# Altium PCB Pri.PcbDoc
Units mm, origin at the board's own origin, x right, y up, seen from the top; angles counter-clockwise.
Board outline 42.69 x 35.5 mm, 4 copper layers (Top Layer, Layer 1, Layer 2, Bottom Layer), stack 1.047 mm thick; 31 components, 16 nets, 112 pads, 246 vias.
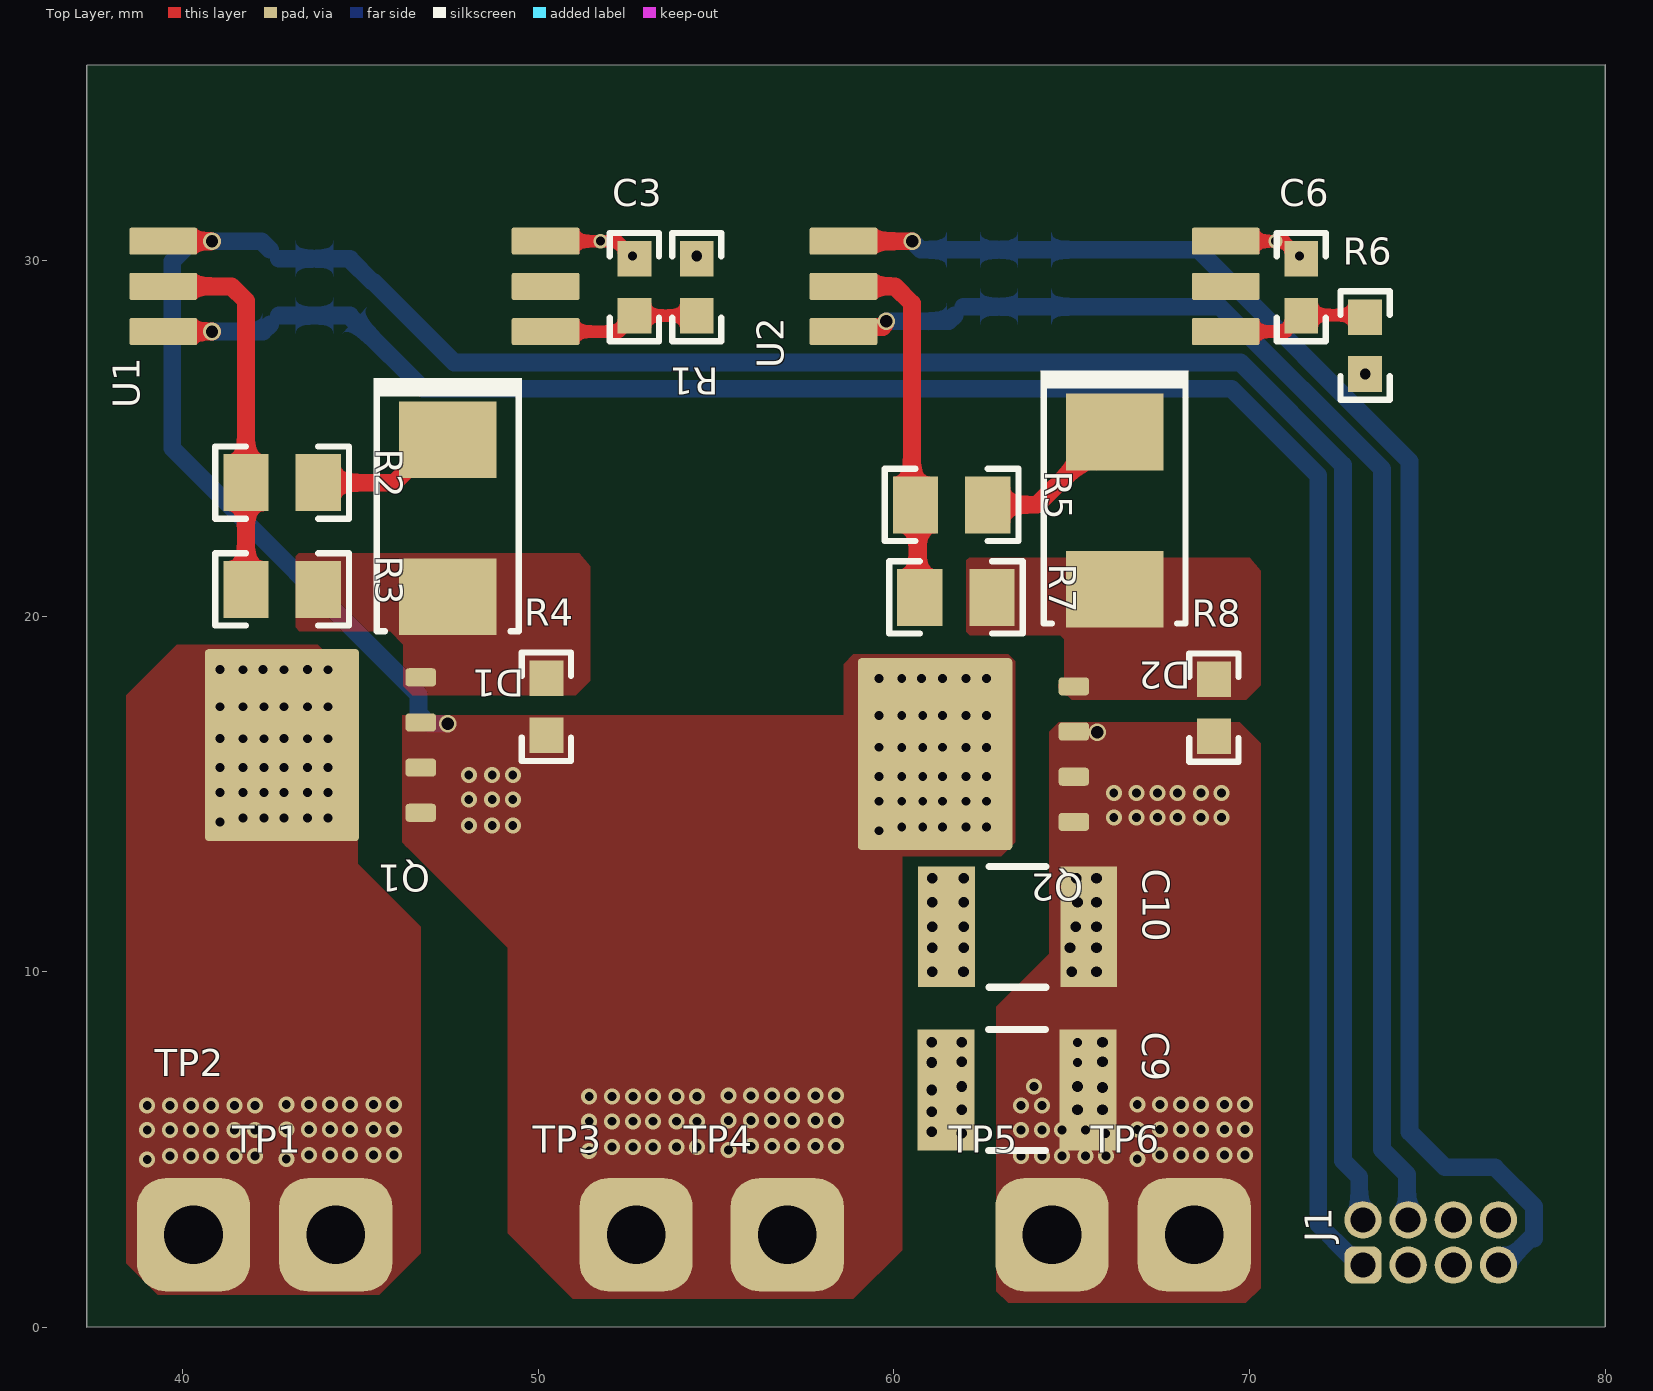
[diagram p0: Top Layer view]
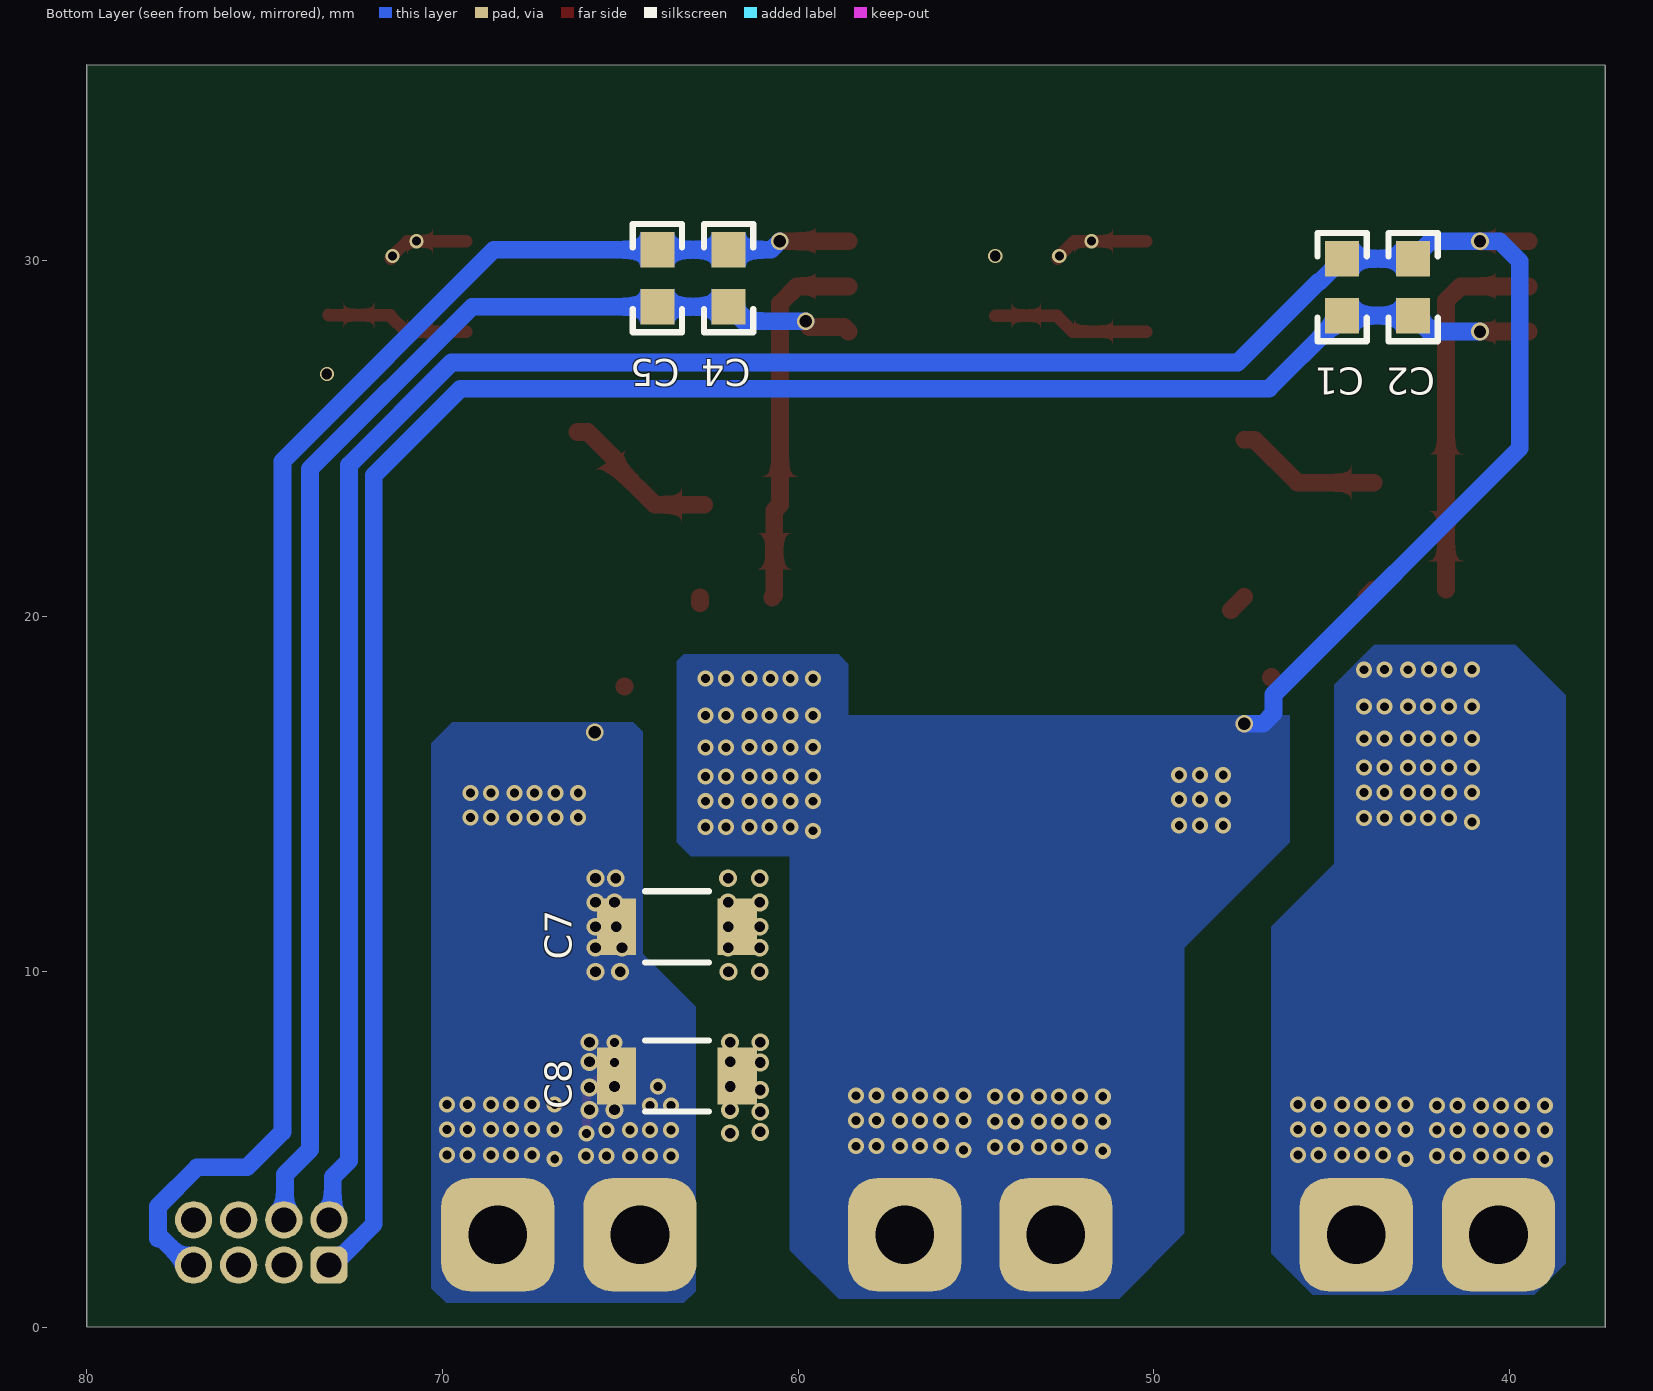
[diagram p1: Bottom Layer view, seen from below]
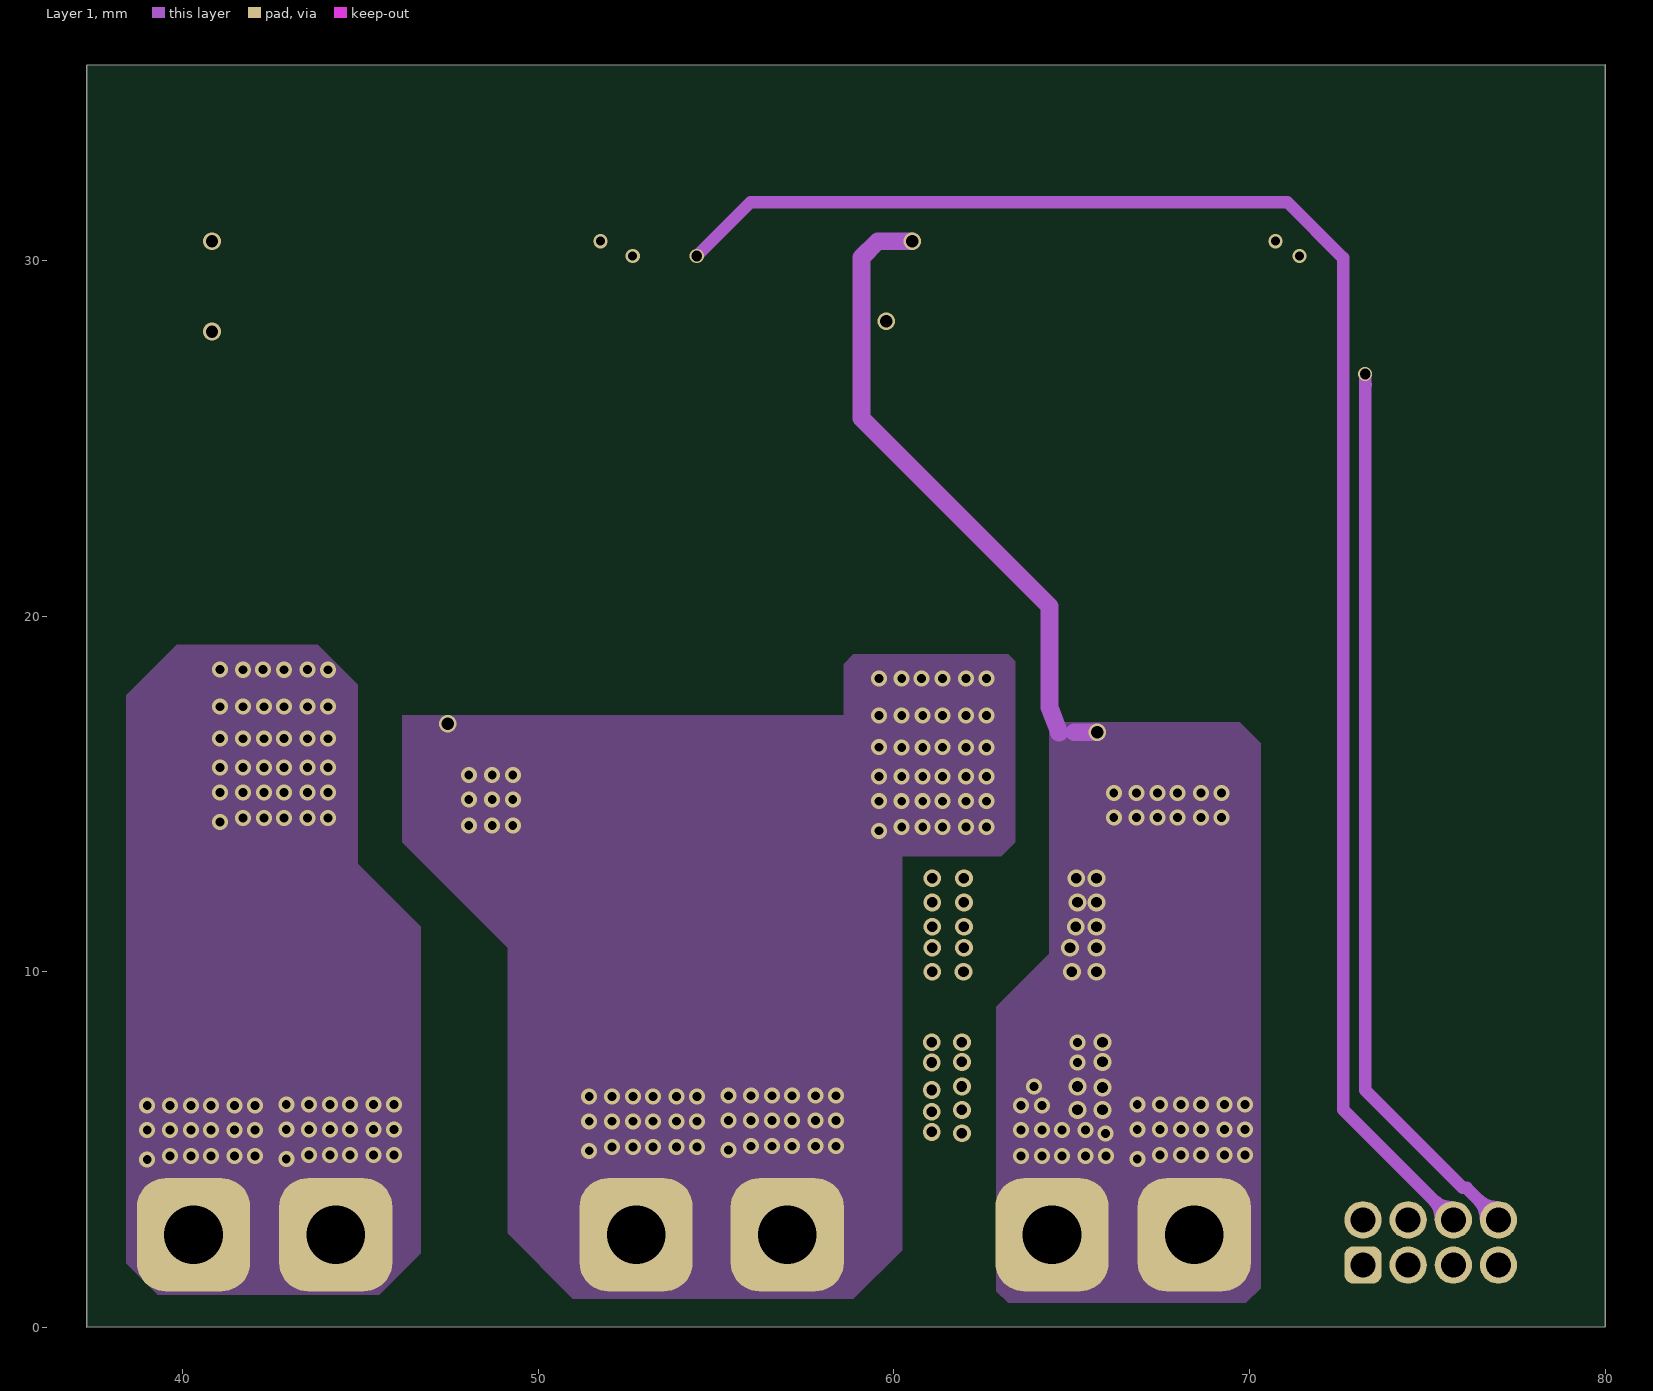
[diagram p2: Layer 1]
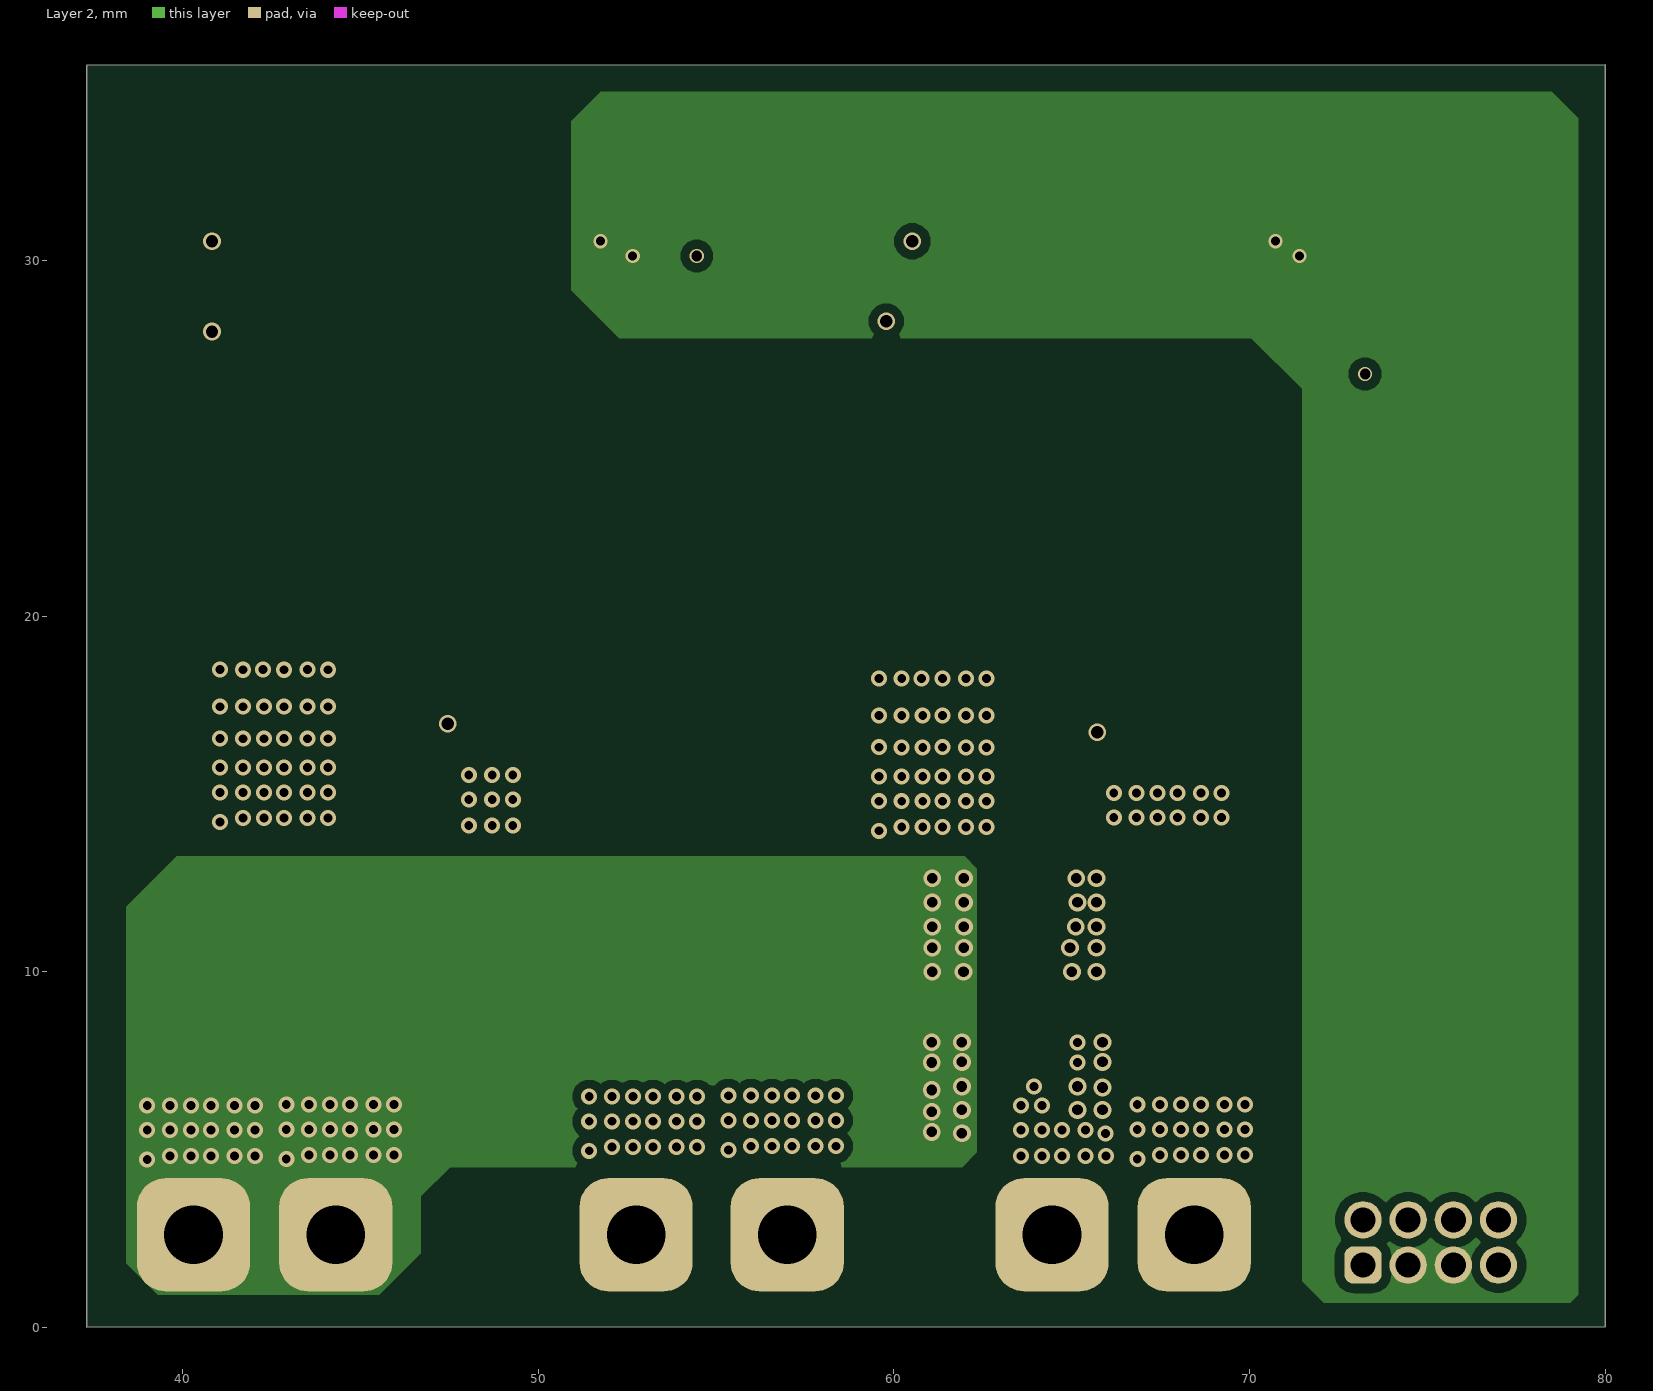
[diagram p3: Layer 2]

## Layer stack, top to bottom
Top Solder: solder mask 0.0102, Solder Resist, Dk 3.5
Top Layer: signal copper 0.07
Dielectric 1: prepreg 0.1168, PP-016, Dk 4.4
Layer 1: signal copper 0.07
Dielectric1: core 0.5334, Core-037, Dk 4.8
Layer 2: signal copper 0.07
Dielectric 2: prepreg 0.1168, PP-016, Dk 4.4
Bottom Layer: signal copper 0.07
Bottom Solder: solder mask 0.0102, Solder Resist, Dk 3.5

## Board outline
37.305,0 80,0.016 80,35.5 37.305,35.484

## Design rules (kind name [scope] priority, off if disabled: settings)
AcuteAngle [All] p1: minimum=4.50000000000000E+0001 checktracksonly=FALSE
AssemblyTestPointUsage [All] p1: valid=2
BoardOutlineClearance BoardOutlineClearance_MountingHoles [OnCopper and InComponentClass('Mounting Holes')] p1: gap=1 ignorepadtopadclearanceinfootprint=FALSE
BoardOutlineClearance BoardOutlineClearance_Poly [OnCopper and IsPoly] p2: gap=0.635 ignorepadtopadclearanceinfootprint=FALSE
BoardOutlineClearance [OnCopper and Not InComponentClass('Logo') and not InComponentClass('FiducialMark') and not InRegion(1000,500,4000,800) and not InPoly] p3: gap=1.016 ignorepadtopadclearanceinfootprint=FALSE
Clearance Clearance_Keepouts [((IsTrack Or IsArc) And Not InPoly) And IsFree and IsKeepOut vs ((IsTrack Or IsArc) And Not InPoly) And IsFree and IsKeepOut] p1: gap=0 ignorepadtopadclearanceinfootprint=FALSE
Clearance Clearance_Poly [InPolygon] p2: gap=0.254 ignorepadtopadclearanceinfootprint=TRUE
Clearance Clearance_FiducialMark [IsKeepOut and InComponentClass('FiducialMark') vs IsPad and InComponentClass('FiducialMark')] p3: gap=0 ignorepadtopadclearanceinfootprint=FALSE
Clearance [All] p4: gap=0.2 ignorepadtopadclearanceinfootprint=TRUE
ComponentClearance ComponentClearance_MountingHoles_FiducialMarks [InComponentClass('Mounting Holes') vs InComponentClass('FiducialMark')] p1: gap=1.27 collisioncheckmode=3 verticalgap=0.254 showdistances=FALSE
ComponentClearance ComponentClearance_Shunt [InComponentClass('Header') vs InComponentClass('Shunt')] p2: gap=0 collisioncheckmode=3 verticalgap=0 showdistances=FALSE
ComponentClearance ComponentClearance_Logo [InComponentClass('Logo')] p3: gap=0.762 collisioncheckmode=3 verticalgap=0.254 showdistances=FALSE
ComponentClearance ComponentClearance_ScrewToNut [(HasFootprint('NY PMS 440 0025 PH')) vs (HasFootprint('Keystone_1902C'))] p4: gap=0.127 collisioncheckmode=3 verticalgap=0.254 showdistances=FALSE
ComponentClearance ComponentClearance_MountingHoles [InComponentClass('Mounting Holes')] p5: gap=2.54 collisioncheckmode=3 verticalgap=2540 showdistances=FALSE
ComponentClearance ComponentClearance_SmallPassives [HasFootprint('0201*') or HasFootprint('0402*') or HasFootprint('0508') or HasFootprint('0603*') or HasFootprint('0612') or HasFootprint('0805*') or HasFootprint('0815*') or HasFootprint('0830*') or HasFootprint('1206*') or HasFootprint('1210*') or HasFootprint('1808*') or HasFootprint('1812*') or HasFootprint('1825*') or HasFootprint('2010*') or HasFootprint('2220*') or HasFootprint('2225*') or HasFootprint('2512*') or HasFootprint('2728*') or HasFootprint('3518*') vs HasFootprint('0201*') or HasFootprint('0402*') or HasFootprint('0508') or HasFootprint('0603*') or HasFootprint('0612') or HasFootprint('0805*') or HasFootprint('0815*') or HasFootprint('0830*') or HasFootprint('1206*') or HasFootprint('1210*') or HasFootprint('1808*') or HasFootprint('1812*') or HasFootprint('1825*') or HasFootprint('2010*') or HasFootprint('2220*') or HasFootprint('2225*') or HasFootprint('2512*') or HasFootprint('2728*') or HasFootprint('3518*')] p6: gap=0.38 collisioncheckmode=3 verticalgap=0.254 showdistances=FALSE
ComponentClearance ComponentClearance_THtoSMT [IsThruComponent vs IsSMTComponent] p7: gap=0.762 collisioncheckmode=3 verticalgap=0.762 showdistances=FALSE
ComponentClearance ComponentClearance_THtoTH [IsThruComponent vs IsThruComponent] p8: gap=0.508 collisioncheckmode=3 verticalgap=0.762 showdistances=FALSE
ComponentClearance [All] p9: gap=0.508 collisioncheckmode=3 verticalgap=0.254 showdistances=FALSE
DiffPairsRouting [All] p1: maxlimit=2.54 minlimit=0.254 mostfreqgap=0.254 toplayer_minwidth=0.381 toplayer_maxwidth=0.381 toplayer_prefwidth=0.381 midlayer1_minwidth=0.381 midlayer1_maxwidth=0.381 midlayer1_prefwidth=0.381 midlayer2_minwidth=0.381 midlayer2_maxwidth=0.381 midlayer2_prefwidth=0.381 bottomlayer_minwidth=0.381 bottomlayer_maxwidth=0.381 bottomlayer_prefwidth=0.381 maxuncoupledlength=25.4
FabricationTestPointUsage TestPointUsage [All] p1: valid=2 allowmultiple=FALSE
FabricationTestpoint Testpoint [All] p1: side=3 testpointundercomponent=TRUE minsize=1.016 maxsize=2.54 preferedsize=1.524 minholesize=0 maxholesize=1.016 preferedholesize=0.813 testpointgrid=0.025 allowsidetop=TRUE allowsidebottom=TRUE usegrid=TRUE gridtolerance=0
FanoutControl Fanout_LCC [IsLCC] p1: bgadir=Out bgaviamode=Centered fanoutstyle=Auto fanoutdirection=Alternating viagrid=0.025 // Fanout_LCC (Default Rule)
FanoutControl Fanout_BGA [IsBGA] p2: bgadir=Out bgaviamode=Centered fanoutstyle=Auto fanoutdirection=Alternating viagrid=0.025 // Fanout_BGA (Default Rule)
FanoutControl Fanout_Default [All] p4: bgadir=Out bgaviamode=Centered fanoutstyle=Auto fanoutdirection=Alternating viagrid=0.025 // Fanout_Default (Default Rule)
FanoutControl Fanout_Small [(CompPinCount < 5)] p5: bgadir=Out bgaviamode=Centered fanoutstyle=Auto fanoutdirection=OutThenIn viagrid=0.025 // Fanout_Small (Default Rule)
HoleSize [All] p1: absolutevalues=TRUE maxlimit=6.375 minlimit=0.2 maxpercent=80.000 minpercent=20.000
MinimumAnnularRing MinimumAnnularRing_ThermalPadVias [IsVia and InAnyComponent] p1: minimumring=0.15
MinimumAnnularRing [All] p2: minimumring=0.2
MinimumSolderMaskSliver MinimumSolderMaskSliver_Logo [InComponentClass('Logo') vs InComponentClass('Logo')] p1: minsoldermaskwidth=0.018
MinimumSolderMaskSliver [All] p2: minsoldermaskwidth=0.1
PlaneConnect [All] p1: planeconnectstyle=Relief reliefexpansion=0.254 reliefentries=4 reliefconductorwidth=0.254 reliefairgap=0.254
PolygonConnect [All] p1: connectstyle=Direct reliefconductorwidth=0.254 reliefentries=4 polygonreliefangle="90 Angle" airgapwidth=0.254
RoomDefinition Pri_mos [InComponentClass('Pri_mos')] p1: confinementstyle=ConfineIn formatcopy=TRUE lockcomponents=FALSE outline -17.577,-38.964 33.223,-38.964 33.223,-13.564 -17.577,-13.564
RoutingLayers [All] p1: top layer_v5=TRUE mid layer 1_v5=FALSE mid layer 2_v5=FALSE bottom layer_v5=TRUE
RoutingVias ThermalPadVias [IsVia and InAnyComponent] p1: holewidth=0.2 width=0.5 viastyle="Through Hole" minholewidth=0.2 minwidth=0.5 maxholewidth=0.33 maxwidth=0.6
RoutingVias [All] p2: holewidth=0.406 width=0.864 viastyle="Through Hole" minholewidth=0.2 minwidth=0.61 maxholewidth=1.016 maxwidth=1.651
SilkToBoardRegionClearance [Not ((IsComment or IsDesignator) And (Hide <> 'False')) and not InRegion(1000,500,4000,800)] p1:
SilkToSilkClearance SilkToSilkClearance_Pb-FreeLogo [(HasFootprint('Pb-Free_Overlay_Medium') OR HasFootprint('Pb-Free_Overlay_Small')) vs (HasFootprint('Pb-Free_Overlay_Medium') OR HasFootprint('Pb-Free_Overlay_Small'))] p1: silktosilkclearance=0
SilkToSilkClearance [All] p2: silktosilkclearance=0.1
SilkToSolderMaskClearance SilkToComponentPadClearance [(IsPad or IsFill or IsRegion) and InAnycomponent] p1: minsilkscreentomaskgap=0.127 clearancetoexposedcopper=TRUE
SilkToSolderMaskClearance "Silk to Solder Mask Opening" [All] p2: minsilkscreentomaskgap=0.1 clearancetoexposedcopper=FALSE
SolderMaskExpansion [All] p1: expansion=0.05 istentingtop=FALSE
UnRoutedNet [All] p1: checkbadconnections=TRUE
Width [All] p1: maxlimit=2.54 minlimit=0.152 preferedwidth=0.254 checkconnectedcopper=TRUE
13 further rules are at their usual default settings.

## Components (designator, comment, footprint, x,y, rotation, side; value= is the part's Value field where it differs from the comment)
C1 "C1608X5R1H104K080AA" 0603 44.705,29.25 r270 bottom value=0.1uF
C2 "GRM188R61H225KE11D" 0603 42.705,29.25 r270 bottom value=2.2uF
C3 "06035A101FAT2A" 0603 52.705,29.25 r90 top value=100pF
C4 "C1608X5R1H104K080AA" 0603 61.955,29.5 r270 bottom value=0.1uF
C5 "GRM188R61H225KE11D" 0603 63.955,29.5 r270 bottom value=2.2uF
C6 "06035A101FAT2A" 0603 71.455,29.25 r90 top value=100pF
C7 "C1206C223KDRACTU" 1206_190 63.41,11.262 r0 bottom value=0.022uF
C8 "C1206C223KDRACTU" 1206_190 63.41,7.064 r0 bottom value=0.022uF
C9 "C1812W104KDRACTU" 1812_254 63.463,6.674 r0 top value=0.1uF
C10 "C1812W104KDRACTU" 1812_254 63.48,11.262 r0 top value=0.1uF
D1 "VS-20BQ030HM3/5BT" SMB 47.455,22.75 r270 top value=30V
D2 "VS-20BQ030HM3/5BT" SMB 66.205,22.965 r270 top value=30V
J1 "GRPB042MWCN-RC" Sullins_GRPB042MWCN 75.095,2.385 r90 top
Q1 "CSD19502Q5B" DNK0008A 43.875,16.372 r180 top value=80V
Q2 "CSD19502Q5B" DNK0008A 62.239,16.118 r180 top value=80V
R1 "TNPW060310R0BEEA" 0603 54.455,29.25 r270 top value=10.0
R2 "MCR10EZPJ000" 0805_HV 42.795,23.75 r0 top value=0
R3 "RC0805JR-071RL" 0805_HV 42.795,20.75 r0 top value=1.0
R4 "RT0603BRD07100KL" 0603 50.23,17.45 r90 top value=100k
R5 "MCR10EZPJ000" 0805_HV 61.624,23.128 r0 top value=0
R6 "TNPW060310R0BEEA" 0603 73.25,27.606 r90 top value=10.0
R7 "RC0805JR-071RL" 0805_HV 61.744,20.523 r0 top value=1.0
R8 "RT0603BRD07100KL" 0603 69.001,17.426 r90 top value=100k
TP1 "3621-0-32-15-00-00-08-0" Mill-Max_3621-0-32-xx-00-00-08-0 44.305,0.215 r0 top
TP2 "3621-0-32-15-00-00-08-0" Mill-Max_3621-0-32-xx-00-00-08-0 40.305,0.215 r0 top
TP3 "3621-0-32-15-00-00-08-0" Mill-Max_3621-0-32-xx-00-00-08-0 52.75,0.215 r0 top
TP4 "3621-0-32-15-00-00-08-0" Mill-Max_3621-0-32-xx-00-00-08-0 57,0.215 r0 top
TP5 "3621-0-32-15-00-00-08-0" Mill-Max_3621-0-32-xx-00-00-08-0 64.445,0.215 r0 top
TP6 "3621-0-32-15-00-00-08-0" Mill-Max_3621-0-32-xx-00-00-08-0 68.445,0.215 r0 top
U1 "UCC23513DWYR" DWY0006A 44.83,29.27 r180 top
U2 "UCC23513DWYR" DWY0006A 63.955,29.27 r180 top

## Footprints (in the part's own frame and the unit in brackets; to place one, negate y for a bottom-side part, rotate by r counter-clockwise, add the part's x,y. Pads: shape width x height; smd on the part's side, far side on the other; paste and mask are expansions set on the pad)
0603 [mm] "0603 from SM-752 data"
  rect 1x0.95 smd: 1(-0.8,0) 2(0.8,0)
  silkscreen extent -1.52,-0.69 1.52,0.69, body extent -0.87,-0.47 0.87,0.47, height 1
0805_HV [mil] "0805 with 30mil clearance between pads"
  rect 50x63 smd: 1(-40,0) 2(40,0)
  silkscreen extent -74,-40 74,40, body extent -43,-29 43,29, height 57
1206_190 [mm] "1206_190"
  rect 1.1x1.6 smd: 1(-1.7,0) 2(1.7,0)
  silkscreen extent -0.9,-1 0.9,1, body extent -1.75,-0.95 1.75,0.95, height 1.9
1812_254 [mm] "SMD, 2-Leads, Body 4.8x3.4mm"
  rect 1.6x3.4 smd: 1(-2,0) 2(2,0)
  silkscreen extent -0.8,-1.7 0.8,1.7, body extent -2.4,-1.7 2.4,1.7, height 2.54
DNK0008A [mm] "SON, 8-Leads, Body 5x6mm"
  rrect39% 0.86x0.51 smd paste-0.05 mask-0.05: 1(-2.82,1.905) 2(-2.82,0.635) 3(-2.82,-0.635) 4(-2.82,-1.905) 5(2.82,-1.905) 6(2.82,-0.635) 7(2.82,0.635) 8(2.82,1.905)
  rrect40% 0.25x0.555 on Top Solder: 9(-0.83,2.372) 9(-0.83,-2.372)
  rrect40% 0.25x0.555 on Top Paste: 9(-0.83,2.372) 9(-0.83,-2.372)
  rrect11% 0.95x1.13 on Top Paste: 9(-0.535,1.33) 9(-0.535,0) 9(-0.535,-1.33) 9(0.615,1.33) 9(0.615,0) 9(0.615,-1.33) 9(1.765,-1.33) 9(1.765,0) 9(1.765,1.33)
  rrect3% 3.58x4 on Top Solder: 9(0.75,0)
  rrect5% 4.34x5.4 smd paste-3 mask-3: 9(1.08,0)
  body extent -3.05,-2.55 3.05,2.55, height 1.06
DWY0006A [mm] "SOIC-6"
  rrect13% 1.905x0.76 smd: 1(-5.375,1.27) 2(-5.375,0) 3(-5.375,-1.27) 4(5.375,-1.27) 5(5.375,0) 6(5.375,1.27)
  body extent -5.75,-2.34 5.75,2.34, height 3.38
Mill-Max_3621-0-32-xx-00-00-08-0 [mm] "PCB Pin, 0.04\" DIA, R/A, Edge-Mount"
  rrect50% 3.18x3.18 hole 1.65: 1(0,2.388)
  body extent -1.59,-5.06 1.59,3.98, height 1.57
SMB [mm] "Molded Diode, 2-Leads, Body 5.4x3.6mm, IPC Medium Density, based on OnSemi component dimensions"
  rect 2.159x2.743 smd: 1(-2.21,0) 2(2.21,0)
  silkscreen extent -3.94,-2.08 3.18,2.08, body extent -2.7,-1.8 2.7,1.8, height 2.32
Sullins_GRPB042MWCN [mm] "Header, 1.27mm, 4x2, R/A, TH"
  rrect50% 1.05x1.05 hole 0.7: 1(-0.635,1.905)
  round 1.05 hole 0.7: 2(0.635,1.905) 3(-0.635,0.635) 4(0.635,0.635) 5(-0.635,-0.635) 6(0.635,-0.635) 7(-0.635,-1.905) 8(0.635,-1.905)
  body extent -5.28,-2.54 0.84,2.54, height 3.4

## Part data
C1 C4: library part CMP-0007010-5, "CAP, CERM, 0.1 uF, 50 V, +/- 10%, X5R, 0603", Cap_Case=0603, Manufacturer=TDK, Supplier Part Number 1=445-7456-1-ND, TempCo=X5R, Tolerance_%=10%, Value1="0.0296 ohm", Value2=50V, ValueDisplayed=0.1uF
C2 C5: library part CMP-0007353-5, "CAP, CERM, 2.2 uF, 50 V, +/- 10%, X5R, 0603", Cap_Case=0603, Manufacturer=MuRata, Supplier Part Number 1=490-10733-1-ND, TempCo=X5R, Tolerance_%=10%, Value1=Unknown, Value2=50V, ValueDisplayed=2.2uF
C3 C6: library part CMP-0006762-4, "CAP, CERM, 100 pF, 50 V, +/- 1%, C0G/NP0, 0603", Cap_Case=0603, Manufacturer=AVX, Supplier Part Number 1=478-6202-1-ND, TempCo=C0G/NP0, Tolerance_%=1%, Value1=Unknown, Value2=50V, ValueDisplayed=100pF
C7 C8: library part CMP-0084048-1, "CAP, CERM, 0.022 µF, 1000 V,+/- 10%, X7R, AEC-Q200 Grade 1, 1206", Cap_Case=1206, Manufacturer=Kemet, TempCo=X7R, Tolerance_%=10%, Value2=1000V, ValueDisplayed=0.022µF
C9 C10: library part CMP-0009326-2, "CAP, CERM, 0.1 uF, 1000 V, +/- 10%, X7R, 1812", Cap_Case=1812, Manufacturer=Kemet, Supplier Part Number 1=399-6523-1-ND, TempCo=X7R, Tolerance_%=10%, Value1=Unknown, Value2=1000V, ValueDisplayed=0.1uF
D1 D2: library part CMP-0028909-2, "Diode, Schottky, 30 V, 2 A, AEC-Q101, SMB", Manufacturer=Vishay-Semiconductor, Value1=2A, Value2=0.47V
J1: library part CMP-0086278-1, "Header, 1.27mm, 4x2, Gold, R/A, TH", Current_A=1A, Manufacturer="Sullins Connector Solutions", Voltage_V=500V
Q1 Q2: library part CMP-0000915-2, "MOSFET, N-CH, 80 V, 100 A, DNK0008A (VSON-CLIP-8)", Alternate Manufacturer=None, Manufacturer="Texas Instruments", Supplier Part Number 1=296-37194-1-ND, Value2="48 nC"
R1 R6: library part CMP-0025687-2, "RES, 10.0, 0.1%, 0.1 W, 0603", Manufacturer=Vishay-Dale, Power_W=100mW, Supplier Part Number 1=TNP10.0AACT-ND, TempCo="25 ppm/C", Tolerance_%=0.1%, Value2=0.1W, Value_Code=10R0, ValueDisplayed=10.0
R2 R5: library part CMP-0020802-2, "RES, 0, 5%, 0.125 W, 0805", Manufacturer=Rohm, Power_W=125mW, Supplier Part Number 1=RHM0.0ARCT-ND, TempCo="400 ppm/C", Tolerance_%=5%, Value2=0.125W, Value_Code=0000, ValueDisplayed=0
R3 R7: library part CMP-0020811-2, "RES, 1.0, 5%, 0.125 W, 0805", Manufacturer="Yageo America", Power_W=125mW, Supplier Part Number 1=311-1.0ARCT-ND, TempCo="200 ppm/C", Tolerance_%=5%, Value2=0.125W, Value_Code=1R00, ValueDisplayed=1.0
R4 R8: library part CMP-0023630-3, "RES, 100 k, 0.1%, 0.1 W, 0603", Manufacturer="Yageo America", Power_W=100mW, Supplier Part Number 1=603-RT0603BRD07100KL, TempCo="25 ppm/C", Tolerance_%=0.1%, Value2=0.1W, Value_Code=100k
TP1 TP2 TP3 TP4 TP5 TP6: library part CMP-0082316-1, "PCB Pin, 0.04\" DIA, Edge-Mount", Manufacturer=Mill-Max, Supplier Part Number 1=575-3621032150000
U1 U2: library part CMP-0081090-2, "5-kVRMS, 3-A Single Channel Isolated Gate Driver with Opto Compatible Input, DWY0006A (SOIC-6)", Alternate Manufacturer="Texas Instruments", Alternate PartNumber=UCC23513DWY

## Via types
v1: diameter 0.45, hole 0.25, Top Layer to Bottom Layer, tented both sides, 198 vias
v2: diameter 0.5, hole 0.3, Top Layer to Bottom Layer, tented both sides, 36 vias
v3: diameter 0.5, hole 0.35, Top Layer to Bottom Layer, tented both sides, 6 vias
v4: diameter 0.4, hole 0.254, Top Layer to Bottom Layer, tented both sides, 4 vias
v5: diameter 0.4, hole 0.3, Top Layer to Bottom Layer, tented both sides, 2 vias

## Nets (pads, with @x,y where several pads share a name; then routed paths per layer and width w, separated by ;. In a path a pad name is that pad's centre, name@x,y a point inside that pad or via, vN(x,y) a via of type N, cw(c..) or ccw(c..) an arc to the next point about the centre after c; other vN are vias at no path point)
+15V_pri: C4.2 C5.2 J1.4 U2.6 | length 38.3
  Top Layer w0.5: U2.6 58.71,28.13 59.683,28.13 v3@59.744,28.19
  Bottom Layer w0.5: v3(59.785,28.29) 61.545,28.29 C4.2@61.705,28.45 ; C4.2 C5.2 69.164,28.7 73.725,24.139 73.725,5 74.43,4.295 74.43,3.05 J1.4
+15V_pri_SW: C1.2 C2.2 J1.1 U1.6 | length 57
  Top Layer w0.5: U1.6 v3(40.825,28)
  Bottom Layer w0.5: v3(40.825,28) 42.255,28 C2.2@42.455,28.2 ; C2.2 C1.2 44.705,28.425 44.93,28.2 44.955,28.2 46.761,26.394 69.49,26.394 71.93,23.954 71.93,2.901 72.814,2.017 72.923,2.017 J1.1
GND_pri: C4.1 C5.1 C7.2 C8.2 C9.2 C10.2 J1.7 Q2.1 Q2.2 Q2.3 R8.1 TP5.1 TP6.1 U2.4 | length 64.1
  Top Layer w0.254: v1(65.16,7.444) 65.948,6.657 v1(65.948,5.455)
  Top Layer w0.5: U2.4 v3@60.505,30.54
  Layer 1 w0.5: v3(60.517,30.54) 59.542,30.54 59.085,30.083 59.085,25.563 64.373,20.275 64.373,17.438 64.646,16.716 ; 65.076,16.735 v3(65.72,16.735)
  Bottom Layer w0.5: v3(60.517,30.54) 60.757,30.3 C4.1 C5.1 68.554,30.3 74.5,24.354 74.5,5.495 75.495,4.5 76.899,4.5 78,3.399 78,2.5 77.899,2.5 77.149,1.75 J1.7
  other v1: 66.843,4.737 63.572,4.818 64.163,4.818 64.722,4.818 65.382,4.818 65.96,4.818 67.483,4.842 68.074,4.842 68.633,4.842 69.293,4.842 69.871,4.842 63.572,5.543 64.163,5.543 64.722,5.543 65.382,5.543 66.843,5.567 67.483,5.567 68.074,5.567 68.633,5.567 69.293,5.567 69.871,5.567 63.572,6.238 64.163,6.238 66.843,6.262 67.483,6.262 68.074,6.262 68.633,6.262 69.293,6.262 69.871,6.262 63.937,6.771 65.16,8.014 66.182,14.333 66.822,14.333 67.413,14.333 67.972,14.333 68.632,14.333 69.21,14.333 66.182,15.028 66.822,15.028 67.413,15.028 67.972,15.028 68.632,15.028 69.21,15.028
  other v2: 65.16,6.114 65.863,6.114 65.863,6.742 65.16,6.771 65.863,7.464 65.863,8.014 65.005,10 65.697,10 64.953,10.672 65.697,10.672 65.11,11.262 65.697,11.262 65.16,11.948 65.697,11.948 65.127,12.626 65.697,12.626
GND_sec: C3.2 C6.2 J1.3 J1.5 U1.3 U2.3 | length 5.1
  Top Layer w0.35: U1.3 52.24,30.54 52.705,30.075 C3.2 ; U2.3 70.99,30.54 71.455,30.075 C6.2
  other v4: 52.655,30.125 71.405,30.125 51.75,30.54 70.73,30.54
NetC1_1: C1.1 C2.1 J1.2 Q1.1 Q1.2 Q1.3 Q2.5 Q2.6 Q2.7 Q2.8 Q2.9@61.159,16.118 R4.1 TP3.1 TP4.1 U1.4 | length 74.8
  Top Layer w0.5: U1.4 v3(40.825,30.54)
  Bottom Layer w0.5: C2.1@42.455,30.3 42.215,30.54 v3(40.825,30.54) 40.27,30.54 39.705,29.975 39.705,24.721 46.63,17.796 46.63,17.264 46.923,16.971 v3(47.455,16.971) ; C2.1 C1.1 44.705,30.025 45.33,29.4 45.367,29.4 47.636,27.131 69.743,27.131 72.63,24.244 72.63,4.684 73.085,4.229 73.085,3.125 J1.2
  other v1: 51.432,4.963 55.343,4.987 52.072,5.068 52.663,5.068 53.222,5.068 53.882,5.068 54.46,5.068 55.983,5.092 56.574,5.092 57.133,5.092 57.793,5.092 58.371,5.092 51.432,5.793 52.072,5.793 52.663,5.793 53.222,5.793 53.882,5.793 54.46,5.793 55.343,5.817 55.983,5.817 56.574,5.817 57.133,5.817 57.793,5.817 58.371,5.817 51.432,6.488 52.072,6.488 52.663,6.488 53.222,6.488 53.882,6.488 54.46,6.488 55.343,6.512 55.983,6.512 56.574,6.512 57.133,6.512 57.793,6.512 58.371,6.512 59.579,13.963 60.219,14.068 60.81,14.068 61.369,14.068 62.029,14.068 62.607,14.068 48.044,14.112 48.705,14.112 49.283,14.112 59.579,14.793 60.219,14.793 60.81,14.793 61.369,14.793 62.029,14.793 62.607,14.793 48.044,14.837 48.705,14.837 49.283,14.837 59.579,15.488 60.219,15.488 60.81,15.488 61.369,15.488 62.029,15.488 62.607,15.488 48.044,15.532 48.705,15.532 49.283,15.532 59.579,16.312 60.219,16.301 60.81,16.301 61.369,16.312 62.029,16.301 62.607,16.301 59.579,17.2 60.219,17.2 60.81,17.2 61.369,17.2 62.029,17.2 62.607,17.2 59.579,18.246 60.219,18.24 60.779,18.246 61.369,18.24 62.029,18.246 62.607,18.24
NetC3_1: C3.1 R1.2 U1.1 | length 4.5
  Top Layer w0.35: U1.1 52.28,28 52.705,28.425 C3.1 R1.2
NetC6_1: C6.1 R6.2 U2.1 | length 4.1
  Top Layer w0.35: U2.1 71.03,28 71.455,28.425 C6.1 71.465,28.46 73.195,28.46 R6.2@73.205,28.47
NetC7_1: C7.1 C8.1 C9.1 C10.1 Q1.5 Q1.6 Q1.7 Q1.8 Q1.9@42.795,16.372 TP1.1 TP2.1
  other v1: 39.002,4.713 42.913,4.737 39.642,4.818 40.233,4.818 40.792,4.818 41.453,4.818 42.03,4.818 43.553,4.842 44.144,4.842 44.703,4.842 45.363,4.842 45.941,4.842 39.002,5.543 39.642,5.543 40.233,5.543 40.792,5.543 41.453,5.543 42.03,5.543 42.913,5.567 43.553,5.567 44.144,5.567 44.703,5.567 45.363,5.567 45.941,5.567 39.002,6.238 39.642,6.238 40.233,6.238 40.792,6.238 41.453,6.238 42.03,6.238 42.913,6.262 43.553,6.262 44.144,6.262 44.703,6.262 45.363,6.262 45.941,6.262 41.055,14.213 41.695,14.318 42.285,14.318 42.844,14.318 43.505,14.318 44.083,14.318 41.055,15.042 41.695,15.042 42.285,15.042 42.844,15.042 43.505,15.042 44.083,15.042 41.055,15.737 41.695,15.737 42.285,15.737 42.844,15.737 43.505,15.737 44.083,15.737 41.055,16.562 41.695,16.551 42.285,16.551 42.844,16.562 43.505,16.551 44.083,16.551 41.055,17.45 41.695,17.45 42.285,17.45 42.844,17.45 43.505,17.45 44.083,17.45 41.055,18.496 41.695,18.49 42.255,18.496 42.844,18.49 43.505,18.496 44.083,18.49
  other v2: 61.91,5.455 61.063,5.495 61.063,6.064 61.91,6.114 61.063,6.674 61.91,6.771 61.063,7.444 61.91,7.464 61.063,8.014 61.91,8.014 61.08,10 61.955,10 61.08,10.672 61.967,10.672 61.08,11.262 61.967,11.262 61.08,11.948 61.967,11.948 61.08,12.626 61.967,12.626
NetD1_1: D1.1 R2.2 | length 4.1
  Top Layer w0.5: R2.2 45.953,23.75 47.163,24.96 D1.1
NetD1_2: D1.2 Q1.4 R3.2 R4.2 | length 0.8
  Top Layer w0.5: R3.2 R3.2@44.021,20.54 ; Q1.4@46.69,18.283 Q1.4 Q1.4@46.7,18.272 ; D1.2 D1.2@47.83,20.165
NetD2_1: D2.1 R5.2 | length 4.5
  Top Layer w0.5: R5.2 64.025,23.128 65.083,24.186 65.083,24.345 65.913,25.175 D2.1
NetD2_2: D2.2 Q2.4 R7.2 R8.2 | length 0.2
  Top Layer w0.5: R7.2@62.76,20.358 R7.2 ; Q2.4@64.878,18.028 Q2.4@64.883,18.023
NetJ1_6: J1.6 R1.1 | length 47.8
  Layer 1 w0.35: v5(54.455,30.125) 55.967,31.637 71.067,31.637 72.63,30.074 72.63,6.123 75.73,3.023 J1.6
NetJ1_8: J1.8 R6.1 | length 25.4
  Layer 1 w0.35: v5(73.25,26.806) 73.26,26.797 73.26,26.507 73.263,26.503 73.25,26.49 73.25,6.67 76,3.92 76.103,3.92 77,3.023 J1.8
NetR2_1: R2.1 R3.1 U1.5 | length 10.6
  Top Layer w0.5: U1.5 41.375,29.27 41.779,28.866 R2.1 R3.1
NetR5_1: R5.1 R7.1 U2.5 | length 10.5
  Top Layer w0.5: U2.5 60.03,29.27 60.505,28.795 60.505,23.128 60.608,23.025 60.668,22.965 60.668,20.584 R7.1
pads on no net: Q1.9@42.11,15.042 Q1.9@42.11,16.372 Q1.9@42.11,17.702 Q1.9@43.26,15.042 Q1.9@43.26,16.372 Q1.9@43.26,17.702 Q1.9@43.125,16.372 Q1.9@44.41,15.042 Q1.9@44.41,16.372 Q1.9@44.41,17.702 Q1.9@44.705,14 Q1.9@44.705,18.745 Q2.9@60.474,14.788 Q2.9@60.474,16.118 Q2.9@60.474,17.448 Q2.9@61.489,16.118 Q2.9@61.624,14.788 Q2.9@61.624,16.118 Q2.9@61.624,17.448 Q2.9@62.774,14.788 Q2.9@62.774,16.118 Q2.9@62.774,17.448 Q2.9@63.069,13.745 Q2.9@63.069,18.49 U1.2 U2.2

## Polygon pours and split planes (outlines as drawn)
NetC1_1 on Top Layer "TOP_LAYER_NETC1_1_P022" (solid, remove dead copper, pour order 22): 58.86,18.922 58.587,18.65 58.587,13.772 59.11,13.25 63.015,13.25 63.41,13.645 63.41,18.732 63.22,18.922
GND_pri on Top Layer "TOP_LAYER_GND_PRI_P017" (solid, remove dead copper, pour order 17): 64.628,17.007 64.373,16.753 64.373,10.5 62.884,9.01 62.884,1.016 63.215,0.685 69.894,0.685 70.309,1.1 70.309,16.425 69.726,17.007
NetC1_1 on Top Layer "TOP_LAYER_NETC1_1_P010" (solid, remove dead copper, pour order 10): 49.134,10.672 49.134,2.638 50.972,0.8 58.86,0.8 60.232,2.172 60.232,16.327 59.346,17.213 46.172,17.213 46.172,13.635
NetC7_1 on Top Layer "TOP_LAYER_NETC7_1_P009" (solid, remove dead copper, pour order 9): 39.837,19.2 38.412,17.775 38.412,1.805 39.303,0.915 45.529,0.915 46.7,2.086 46.7,11.262 44.93,13.032 44.93,18.067 43.797,19.2
NetD2_2 on Top Layer "TOP_LAYER_NETD2_2_P002" (solid, remove dead copper, pour order 2): 62.113,21.644 62.034,21.564 62.034,19.557 62.137,19.453 64.684,19.453 64.792,19.344 64.792,17.866 65.005,17.653 69.909,17.653 70.309,18.053 70.309,21.272 69.999,21.644
NetC1_1 on Top Layer "TOP_LAYER_NETC1_1_P001" (solid, remove dead copper, pour order 1): 46.557,17.213 46.172,16.971 46.172,13.635 46.307,13.5 60.053,13.5 60.469,13.916 60.469,16.802 60.058,17.213
NetD1_2 on Top Layer "TOP_LAYER_NETD1_2_P000" (solid, remove dead copper, pour order 0): 43.26,21.766 43.18,21.686 43.18,19.679 43.284,19.575 45.83,19.575 46.205,19.2 46.205,18.023 46.453,17.775 51.055,17.775 51.455,18.175 51.455,21.393 51.146,21.766
NetC7_1 on Layer 2 "LAYER_2_NETC7_1_P023" (solid, remove dead copper, pour order 23): 39.303,0.915 38.412,1.805 38.412,11.825 39.837,13.25 61.986,13.25 62.336,12.9 62.336,4.915 61.921,4.5 47.52,4.5 46.7,3.68 46.7,2.086 45.529,0.915
GND_sec on Layer 2 "LAYER_2_GND_SEC_P005" (solid, remove dead copper, pour order 5): 51.755,34.75 50.921,33.916 50.921,29.164 52.275,27.809 70.054,27.809 71.476,26.388 71.476,1.296 72.086,0.685 79.02,0.685 79.25,0.915 79.25,34 78.5,34.75
GND_pri on Bottom Layer "BOTTOM_LAYER_GND_PRI_P021" (solid, remove dead copper, pour order 21): 64.628,17.007 64.373,16.752 64.373,10.5 62.884,9.01 62.884,1.016 63.215,0.685 69.894,0.685 70.309,1.1 70.309,16.425 69.726,17.007
NetC1_1 on Bottom Layer "BOTTOM_LAYER_NETC1_1_P014" (solid, remove dead copper, pour order 14): 58.86,18.922 58.587,18.65 58.587,13.772 59.11,13.25 63.015,13.25 63.41,13.645 63.41,18.732 63.22,18.922
NetC1_1 on Bottom Layer "BOTTOM_LAYER_NETC1_1_P013" (solid, remove dead copper, pour order 13): 49.134,10.672 49.134,2.638 50.972,0.8 58.86,0.8 60.232,2.172 60.232,16.327 59.346,17.213 46.172,17.213 46.172,13.635
NetC7_1 on Bottom Layer "BOTTOM_LAYER_NETC7_1_P006" (solid, remove dead copper, pour order 6): 39.837,19.2 38.412,17.775 38.412,1.805 39.303,0.915 45.529,0.915 46.7,2.086 46.7,11.262 44.93,13.032 44.93,18.067 43.797,19.2
GND_pri on Layer 1 "LAYER_1_GND_PRI_P019" (solid, remove dead copper, pour order 19): 64.628,17.007 64.373,16.752 64.373,10.5 62.884,9.01 62.884,1.016 63.215,0.685 69.894,0.685 70.309,1.1 70.309,16.425 69.726,17.007
NetC1_1 on Layer 1 "LAYER_1_NETC1_1_P016" (solid, remove dead copper, pour order 16): 58.86,18.922 58.587,18.65 58.587,13.772 59.11,13.25 63.015,13.25 63.41,13.645 63.41,18.732 63.22,18.922
NetC1_1 on Layer 1 "LAYER_1_NETC1_1_P012" (solid, remove dead copper, pour order 12): 49.134,10.672 49.134,2.638 50.972,0.8 58.86,0.8 60.232,2.172 60.232,16.327 59.346,17.213 46.172,17.213 46.172,13.635
NetC7_1 on Layer 1 "LAYER_1_NETC7_1_P008" (solid, remove dead copper, pour order 8): 39.837,19.2 38.412,17.775 38.412,1.805 39.303,0.915 45.529,0.915 46.7,2.086 46.7,11.262 44.93,13.032 44.93,18.067 43.797,19.2

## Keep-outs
Keep-Out Layer:
  text ".Layer_Name" at 14.656,-21.806 h1.52

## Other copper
Top Layer:
  text ".Layer_Name" at 14.656,-21.806 h1.52
Bottom Layer:
  text ".Layer_Name" at 14.656,-21.806 h1.52

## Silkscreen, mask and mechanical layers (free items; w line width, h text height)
Top Overlay:
  text ".Layer_Name" at 14.656,-21.806 h1.52
Bottom Overlay:
  text ".Layer_Name" at 14.656,-21.806 h1.52
Top Paste:
  text ".Layer_Name" at 14.656,-21.806 h1.52
Bottom Paste:
  text ".Layer_Name" at 14.656,-21.806 h1.52
Top Solder:
  text ".Layer_Name" at 14.656,-21.806 h1.52
  text ".Layer_Name" at 14.656,-21.806 h1.52
Bottom Solder:
  rectangle: 40.291,13.512 45.013,19.107
  rectangle: 58.741,13.25 63.463,18.845
  text ".Layer_Name" at 14.656,-21.806 h1.52
Drill Guide:
  text ".Layer_Name" at 14.656,-21.806 h1.52
M1 Board Outline:
  the board outline again, w0.254
  text ".Layer_Name" at 14.656,-21.806 h1.52
M2 Board Dimensions:
  rectangle: 0,-6.985 3.175,-3.81
  rectangle: 3.175,-10.16 12.7,-6.985
  lines w0.178: 0,-6.985 25.4,-6.985 ; 3.175,-10.16 3.175,-3.81 ; 6.35,-10.16 6.35,-3.81 ; 12.7,-10.16 12.7,-3.81 ; 19.05,-10.16 19.05,-3.81 ; 0,-10.16 25.4,-10.16 25.4,-3.81 0,-3.81 0,-10.16
  text ".Layer_Name" at 14.656,-21.806 h1.52
M3 3D STEP Top:
  text ".Layer_Name" at 14.656,-21.806 h1.52
M4 3D STEP Bottom:
  text ".Layer_Name" at 14.656,-21.806 h1.52
M5 Assembly Top:
  lines w0.254: -7.417,-23.626 160.223,-23.626 ; -7.417,-18.462 160.274,-18.462 ; -7.417,-13.297 -7.417,-28.791 94.31,-28.791 160.274,-28.791 160.274,-13.297 -7.404,-13.297 -7.404,-28.791 32.614,-28.791 ; 55.194,-28.791 55.194,-13.297 ; 87.376,-18.462 87.376,-13.297 ; 108.712,-18.462 108.712,-13.297 ; 124.511,-28.956 124.511,-23.804
  text "COMPONENTS MARKED 'DNP' SHOULD NOT BE POPULATED." at 29.299,-8.09 h1.52
  text "ASSEMBLY VARIANT:" at 29.286,-11.024 h1.52
  text ".VariantName" at 55.601,-11.024 h1.52
  text "PCB VIEWED FROM TOP SIDE" at -5.804,-16.654 h1.52
  text "BOARD #:" at 57.099,-16.654 h1.52
  text ".PRJ_Number" at 70.955,-16.654 h1.52
  text "REV:" at 92.405,-16.654 h1.52
  text ".PCB_Rev" at 99.809,-16.654 h1.52
  text "SVN REV:" at 113.69,-16.654 h1.52
  text ".VersionControl_RevNumber" at 126.543,-16.654 h1.52
  text "TID #:" at 57.099,-21.819 h1.52
  text ".TID" at 70.955,-21.819 h1.52
  text "PLOT NAME =" at -5.804,-27.034 h1.52
  text ".plot_File_Name" at 14.656,-27.034 h1.52
  text "GENERATED    :" at 57.15,-27.034 h1.52
  text ".Print_Date" at 79.235,-27.034 h1.52
  text ".Print_Time" at 97.752,-27.034 h1.52
  text "TEXAS INSTRUMENTS" at 129.87,-27.034 h1.52
M6 Assembly Bottom:
  lines w0.254: -7.429,-18.474 160.261,-18.474 ; -7.379,-23.639 160.261,-23.639 ; 28.334,-28.969 28.334,-23.817 ; 44.133,-18.474 44.133,-13.31 ; 65.468,-18.474 65.468,-13.31 ; 97.65,-28.804 97.65,-13.31 ; 120.231,-28.804 160.249,-28.804 160.249,-13.31 -7.429,-13.31 -7.429,-28.804 58.534,-28.804 160.261,-28.804 160.261,-13.31
  text "COMPONENTS MARKED 'DNP' SHOULD NOT BE POPULATED." at 154.991,-8.077 h1.52
  text ".VariantName" at 128.473,-11.024 h1.52
  text "ASSEMBLY VARIANT:" at 154.864,-11.024 h1.52
  text ".VersionControl_RevNumber" at 26.302,-16.667 h1.52
  text "SVN REV:" at 39.154,-16.667 h1.52
  text ".PCB_Rev" at 53.035,-16.667 h1.52
  text "REV:" at 60.439,-16.667 h1.52
  text ".PRJ_Number" at 81.89,-16.667 h1.52
  text "BOARD #:" at 95.745,-16.667 h1.52
  text "PCB VIEWED FROM BOTTOM SIDE" at 158.648,-16.667 h1.52
  text ".TID" at 81.89,-21.831 h1.52
  text "TID #:" at 95.745,-21.831 h1.52
  text "TEXAS INSTRUMENTS" at 22.974,-27.047 h1.52
  text ".Print_Time" at 55.093,-27.047 h1.52
  text ".Print_Date" at 73.609,-27.047 h1.52
  text "GENERATED    :" at 95.694,-27.047 h1.52
  text ".plot_File_Name" at 138.189,-27.047 h1.52
  text "PLOT NAME =" at 158.648,-27.047 h1.52
M9 Title Sheet:
  drawing of 57 lines, arcs and shapes, not listed
  text "1" at 18.792,204.127 h1.78
  text "2" at 82.182,204.127 h1.78
  text "3" at 145.411,204.127 h1.78
  text "4" at 209.08,204.127 h1.78
  text "5" at 272.555,204.127 h1.78
  text "6" at 336.182,204.127 h1.78
  text "A" at -10.579,175.095 h1.78
  text "A" at 365.341,175.095 h1.78
  text "B" at -10.579,114.643 h1.78
  text "B" at 365.341,114.643 h1.78
  text "C" at -10.579,54.318 h1.78
  text "C" at 365.341,54.318 h1.78
  text "PROJECT TITLE:" at 288.125,7.048 h1.14
  text ".PRJ_Title" at 289.395,3.662 h1.78
  text "DESIGNED FOR:" at 288.125,-0.597 h1.14
  text ".PRJ_Customer" at 289.395,-4.153 h1.78
  text "D" at -10.579,-5.88 h1.78
  text "D" at 365.341,-5.88 h1.78
  text "FILE NAME:" at 288.125,-8.217 h1.14
  text ".PCB_File_Name_No_Path" at 289.395,-11.265 h1.78
  text "Texas Instruments (TI) and/or its licensors do not warrant the accuracy or completeness of this specification" at 161.9,-15.376 h1.14
  text "ENGINEER:" at 288.125,-15.583 h1.14
  text "LAYOUT BY:" at 326.352,-15.583 h1.14
  text "or any information contained therein. TI and/or its licensors do not warrant that this design will meet" at 160.757,-18.237 h1.14
  text ".PRJ_Engineer" at 289.395,-19.52 h1.78
  text ".PCB_Layout" at 327.635,-19.52 h1.78
  text "the specifications, will be suitable for your application or fit for any particular purpose, or will operate in" at 160.757,-21.099 h1.14
  text ".Layer_Name" at 14.656,-21.806 h1.52
  text "ALTIUM DESIGNER VERSION:" at 326.352,-23.457 h1.14
  text "an implementation. TI and/or its licensors do not warrant that the design is production worthy. You should" at 160.757,-23.961 h1.14
  text "completely validate and test your design implementation to confirm the system functionality for your application." at 161.9,-26.822 h1.14
  text ".print_Scale" at 289.395,-26.843 h1.78
  text ".Application_BuildNumber" at 327.635,-26.843 h1.78
  text "1" at 18.792,-32.093 h1.78
  text "2" at 82.182,-32.093 h1.78
  text "3" at 145.411,-32.093 h1.78
  text "4" at 209.08,-32.093 h1.78
  text "5" at 272.555,-32.093 h1.78
  text "6" at 336.182,-32.093 h1.78
M10 Fab Notes:
  drawing of 189 lines, arcs and shapes, not listed
  text "DESIGN INFORMATION" at 314.503,161.447 h1.52
  text "MIN. TRACK WIDTH:" at 298.131,158.091 h1.52
  text "8" at 325.976,158.091 h1.52
  text "MIL" at 329.907,158.091 h1.52
  text "7.874" at 321.75,155 h1.52
  text "MIN. CLEARANCE:" at 298.131,154.938 h1.52
  text "MIL" at 329.907,154.938 h1.52
  text "MIN. VIA PAD SIZE:" at 298.131,151.785 h1.52
  text "24" at 325.214,151.785 h1.52
  text "MIL" at 329.907,151.785 h1.52
  text "0.05mm (2MIL)" at 315.784,148.486 h1.52
  text "MINIMUM ANNULAR RING" at 289.769,148.277 h1.52
  text "EXTERNAL" at 333.768,148.277 h1.52
  text "PER" at 294.849,145.48 h1.52
  text "IPC-D-275 CLASS 2 LEVEL C" at 300.437,145.48 h1.52
  text "MIL, HOLES" at 338.238,142.928 h1.52
  text "+/-" at 328.27,142.709 h1.52
  text "+/-" at 349.961,142.709 h1.52
  text "REGISTRATION TOLERANCES:" at 289.769,142.682 h1.52
  text "METAL" at 320.243,142.682 h1.52
  text "5" at 334.879,142.683 h1.52
  text "3" at 356.037,142.683 h1.52
  text "MIL" at 358.99,142.682 h1.52
  text "HOLE SIZE TOLERANCE (UNLESS OTHERWISE SPECIFIED):" at 289.769,140.185 h1.52
  text "+/-" at 349.961,140.112 h1.52
  text "3" at 356.037,140.085 h1.52
  text "MIL" at 358.99,140.085 h1.52
  text "MATERIAL:" at 287.87,136.589 h1.52
  text "FR-4 High Tg" at 312.926,133.324 h1.52
  text "X" at 309.257,133.122 h1.52
  text "FR-4" at 298.563,133.007 h1.52
  text "OTHER" at 336.358,133.007 h1.52
  text "62 MIL (1.6mm) +/-10%" at 306.694,129.374 h1.52
  text "X" at 303.643,129.312 h1.52
  text "THICKNESS:" at 289.769,129.165 h1.52
  text "OTHER" at 339.33,129.165 h1.52
  text "TOLERANCE:" at 289.769,125.652 h1.52
  text "X" at 311.314,125.652 h1.52
  text "ANSI IPC-6012 TYPE 3 CLASS 2" at 315.836,125.652 h1.52
  text "OTHER +/-" at 315.835,121.989 h1.52
  text "BOW & TWIST:" at 289.769,118.302 h1.52
  text "X" at 311.314,118.302 h1.52
  text "ANSI IPC-6012 TYPE 3 CLASS 2" at 315.836,118.302 h1.52
  text "OTHER +/-" at 315.835,114.576 h1.52
  text "DRILLING:" at 287.87,111.258 h1.52
  text "NC_DRILL FILES" at 332.599,108.586 h1.52
  text "REFERENCE:" at 289.769,108.486 h1.52
  text "X" at 306.463,108.484 h1.52
  text "AS SHOWN" at 310.984,108.486 h1.52
  text "X" at 329.348,108.486 h1.52
  text "OTHER" at 340.168,104.873 h1.52
  text "PTH COPPER THICKNESS:" at 289.761,104.783 h1.52
  text "X" at 318.697,104.783 h1.52
  text "20-30 um" at 321.948,104.783 h1.52
  text "BOARD FINISH:" at 287.87,101.034 h1.52
  text "SILKSCREEN:" at 291.812,98.237 h1.52
  text "X" at 316.14,98.237 h1.52
  text "TOP" at 319.112,98.237 h1.52
  text "X" at 329.094,98.237 h1.52
  text "BOTTOM" at 332.091,98.237 h1.52
  text "SILKSCREEN COLOR:" at 291.812,94.295 h1.52
  text "X" at 316.115,94.295 h1.52
  text "WHITE" at 319.112,94.295 h1.52
  text "OTHER" at 332.091,94.295 h1.52
  text "X" at 319.442,90.652 h1.52
  text "GREEN" at 322.439,90.652 h1.52
  text "OTHER" at 338.136,90.652 h1.52
  text "SOLDER RESIST COLOR:" at 291.812,90.477 h1.52
  text "X" at 319.442,86.734 h1.52
  text "MATTE" at 322.439,86.734 h1.52
  text "SEMI-GLOSS" at 338.125,86.717 h1.52
  text "IMMERSION GOLD (ENIG)" at 314.819,82.345 h1.52
  text "ENEPIG" at 348.793,82.162 h1.52
  text "SURFACE FINISH:" at 287.87,82.136 h1.52
  text "X" at 310.298,82.136 h1.52
  text "IMM. TIN/SILVER OR EQUIV" at 296.24,78.649 h1.52
  text "OTHER" at 332.599,78.549 h1.52
  text "ARRAY/PANEL:" at 287.87,74.602 h1.52
  text "CUT AND TRIM PER M1 BOARD OUTLINE" at 314.819,74.393 h1.52
  text "N.C. ROUTE" at 314.819,70.94 h1.52
  text "X" at 332.295,70.94 h1.52
  text "V. SCORE" at 336.816,70.94 h1.52
  text "CERTIFICATION:" at 287.87,67.66 h1.52
  text "MATERIALS AND WORKMANSHIP FOR ALL PCBS" at 306.285,67.66 h1.52
  text "TO MEET OR EXCEED THE REQUIREMENTS OF:" at 306.285,65.271 h1.52
  text "X" at 297.078,62.003 h1.52
  text "ANSI IPC-A-600F CLASS ->" at 300.329,62.003 h1.52
  text "X" at 342.188,62.003 h1.52
  text "2" at 344.982,62.003 h1.52
  text "1" at 336.981,61.965 h1.52
  text "3" at 353.973,61.965 h1.52
  text "X" at 317.702,58.252 h1.52
  text "RoHS" at 320.953,58.252 h1.52
  text "OTHER" at 337.321,58.252 h1.52
  text "PER ORDER" at 347.407,58.252 h1.52
  text "ALL BOARDS MUST MEET OR EXCEED UL94-V0 REQUIREMENTS." at 288.569,54.345 h1.52
  text "PCB MUST BEAR THE UL94V-0 UL REGISTERED MATERIAL ID NUMBER" at 288.569,51.397 h1.52
  text "ADDITIONAL REQUIREMENTS:" at 287.87,47.094 h1.52
  text "MICROSECTION:" at 289.769,44.373 h1.52
  text "YES" at 312.775,44.373 h1.52
  text "REQUIRED" at 334.657,40.707 h1.52
  text "BARE BOARD ELEC. TEST:" at 289.769,40.634 h1.52
  text "NONE" at 322.935,40.634 h1.52
  text "X" at 331.66,40.634 h1.52
  text "PER ORDER" at 349.693,40.634 h1.52
  text "XX MIL VIAS REQUIRE NON-CONDUCTIVE FILL AND PLANARIZE" at 294.04,35.428 h1.5
  text "XX MIL VIAS REQUIRE CONDUCTIVE FILL AND PLANARIZE" at 294.243,32.787 h1.52
  text "OUTER XX MIL TRACES REQUIRE 50 OHM SINGLE-ENDED IMPEDANCE" at 294.218,28.637 h1.47
  text "LAYER 2 & 3 (INNER LAYERS) XX MIL WIDE, XX MIL SPACE / TRACES REQUIRE 100 OHM DIFFERENTIAL IMPEDANCE" at 294.015,22.65 h1.52
  text ".Layer_Name" at 14.656,-21.806 h1.52
M11 Gerber Information:
  lines w0.254: -7.417,-23.626 160.223,-23.626 ; -7.417,-18.462 160.274,-18.462 ; -7.417,-13.297 -7.417,-28.791 94.31,-28.791 160.274,-28.791 160.274,-13.297 -7.404,-13.297 -7.404,-28.791 32.614,-28.791 ; 55.194,-28.791 55.194,-13.297 ; 87.376,-18.462 87.376,-13.297 ; 108.712,-18.462 108.712,-13.297 ; 124.511,-28.956 124.511,-23.804
  text "ALL ARTWORK VIEWED FROM TOP SIDE" at -5.804,-16.654 h1.52
  text "BOARD #:" at 57.099,-16.654 h1.52
  text ".PRJ_Number" at 70.955,-16.654 h1.52
  text "REV:" at 92.405,-16.654 h1.52
  text ".PCB_Rev" at 99.809,-16.654 h1.52
  text "SVN REV:" at 113.69,-16.654 h1.52
  text ".VersionControl_RevNumber" at 126.543,-16.654 h1.52
  text "LAYER NAME =" at -5.804,-21.806 h1.52
  text "TID #:" at 57.099,-21.819 h1.52
  text ".TID" at 70.955,-21.819 h1.52
  text "PLOT NAME =" at -5.804,-27.034 h1.52
  text ".plot_File_Name" at 14.656,-27.034 h1.52
  text "GENERATED    :" at 57.15,-27.034 h1.52
  text ".Print_Date" at 79.235,-27.034 h1.52
  text ".Print_Time" at 97.752,-27.034 h1.52
  text "TEXAS INSTRUMENTS" at 129.87,-27.034 h1.52
M12 Stackup:
  drawing of 295 lines, arcs and shapes, not listed
  text "Layer" at 249.469,200.023 h1.52
  text "Name" at 259.88,200.023 h1.52
  text "Material" at 283.496,200.023 h1.52
  text "Thickness" at 305.334,200.023 h1.52
  text "Constant" at 321.84,200.023 h1.52
  text "Board Layer Stack" at 336.314,200.023 h1.52
  text "Top Overlay" at 259.88,196.975 h1.52
  text "Top Solder" at 259.88,193.927 h1.52
  text "Solder Resist" at 283.496,193.927 h1.52
  text "0.40mil" at 305.334,193.927 h1.52
  text "3.5" at 321.84,193.927 h1.52
  text "1" at 249.469,190.879 h1.52
  text "Top Layer" at 259.88,190.879 h1.52
  text "2.76mil" at 305.334,190.879 h1.52
  text "Dielectric 1" at 259.88,187.831 h1.52
  text "PP-016" at 283.496,187.831 h1.52
  text "4.60mil" at 305.334,187.831 h1.52
  text "4.4" at 321.84,187.831 h1.52
  text "2" at 249.469,184.783 h1.52
  text "Layer 1" at 259.88,184.783 h1.52
  text "CF-004" at 283.496,184.783 h1.52
  text "2.76mil" at 305.334,184.783 h1.52
  text "Dielectric1" at 259.88,181.735 h1.52
  text "Core-037" at 283.496,181.735 h1.52
  text "21.00mil" at 305.334,181.735 h1.52
  text "4.8" at 321.84,181.735 h1.52
  text "3" at 249.469,178.687 h1.52
  text "Layer 2" at 259.88,178.687 h1.52
  text "CF-004" at 283.496,178.687 h1.52
  text "2.76mil" at 305.334,178.687 h1.52
  text "Dielectric 2" at 259.88,175.639 h1.52
  text "PP-016" at 283.496,175.639 h1.52
  text "4.60mil" at 305.334,175.639 h1.52
  text "4.4" at 321.84,175.639 h1.52
  text "4" at 249.469,172.591 h1.52
  text "Bottom Layer" at 259.88,172.591 h1.52
  text "2.76mil" at 305.334,172.591 h1.52
  text "Bottom Solder" at 259.88,169.543 h1.52
  text "Solder Resist" at 283.496,169.543 h1.52
  text "0.40mil" at 305.334,169.543 h1.52
  text "3.5" at 321.84,169.543 h1.52
  text "Bottom Overlay" at 259.88,166.495 h1.52
  text ".Layer_Name" at 14.656,-21.806 h1.52
M13 Component Bodies Top:
  text ".Layer_Name" at 14.656,-21.806 h1.52
M14 Component Bodies Bottom:
  text ".Layer_Name" at 14.656,-21.806 h1.52
M15 Courtyards Top:
  text ".Layer_Name" at 14.656,-21.806 h1.52
M16 Courtyards Bottom:
  text ".Layer_Name" at 14.656,-21.806 h1.52
Drill Drawing:
  circle w0.254: c136.238,70.942 r0.702
  lines w0.254: 135.537,67.083 136.94,67.083 136.94,68.486 135.537,68.486 135.537,67.083 ; 135.537,73.749 135.888,73.749 136.238,73.398 136.589,73.749 136.94,73.749 136.589,74.1 136.94,74.451 136.589,74.451 136.238,74.802 135.888,74.451 135.537,74.451 135.888,74.1 135.537,73.749 ; 135.537,77.959 136.94,77.959 136.238,76.556 135.537,77.959 ; 135.537,79.714 136.238,80.065 136.94,79.714 136.589,80.415 136.94,81.117 136.238,80.766 135.537,81.117 135.888,80.415 135.537,79.714 ; 135.537,83.222 135.888,83.222 135.888,82.871 136.589,82.871 136.589,83.222 136.94,83.222 136.94,83.924 136.589,83.924 136.589,84.275 135.888,84.275 135.888,83.924 135.537,83.924 135.537,83.222
  lines w0.305: 134.264,66.136 216.344,66.136 ; 134.264,85.082 216.344,85.082 ; 142.846,62.978 142.846,88.24 ; 151.279,62.978 151.279,88.24 ; 167.448,62.978 167.448,88.24 ; 174.03,62.978 174.03,88.24 ; 183.559,62.978 183.559,88.24 ; 201.957,62.978 201.957,88.24 ; 134.264,62.978 216.344,62.978 216.344,88.24 134.264,88.24 134.264,62.978
  text "Symbol" at 136.159,86.029 h1.83
  text "Quantity" at 143.793,86.029 h1.83
  text "Finished Hole Size" at 152.226,86.029 h1.83
  text "Plated" at 168.395,86.029 h1.83
  text "Hole Type" at 174.977,86.029 h1.83
  text "Drill Layer Pair" at 184.506,86.029 h1.83
  text "Hole Tolerance" at 202.904,86.029 h1.83
  text "198" at 143.793,82.871 h1.52
  text "9.84mil (0.250mm)" at 152.226,82.871 h1.52
  text "PTH" at 168.395,82.871 h1.52
  text "Round" at 174.977,82.871 h1.52
  text "Top Layer - Bottom Layer" at 184.506,82.871 h1.52
  text "4" at 143.793,79.714 h1.52
  text "10.00mil (0.254mm)" at 152.226,79.714 h1.52
  text "PTH" at 168.395,79.714 h1.52
  text "Round" at 174.977,79.714 h1.52
  text "Top Layer - Bottom Layer" at 184.506,79.714 h1.52
  text "38" at 143.793,76.556 h1.52
  text "11.81mil (0.300mm)" at 152.226,76.556 h1.52
  text "PTH" at 168.395,76.556 h1.52
  text "Round" at 174.977,76.556 h1.52
  text "Top Layer - Bottom Layer" at 184.506,76.556 h1.52
  text "6" at 143.793,73.398 h1.52
  text "13.78mil (0.350mm)" at 152.226,73.398 h1.52
  text "PTH" at 168.395,73.398 h1.52
  text "Round" at 174.977,73.398 h1.52
  text "Top Layer - Bottom Layer" at 184.506,73.398 h1.52
  text "8" at 143.793,70.241 h1.52
  text "27.56mil (0.700mm)" at 152.226,70.241 h1.52
  text "PTH" at 168.395,70.241 h1.52
  text "Round" at 174.977,70.241 h1.52
  text "Top Layer - Bottom Layer" at 184.506,70.241 h1.52
  text "+/-1.97mil" at 202.904,70.241 h1.52
  text "6" at 143.793,67.083 h1.52
  text "64.96mil (1.650mm)" at 152.226,67.083 h1.52
  text "PTH" at 168.395,67.083 h1.52
  text "Round" at 174.977,67.083 h1.52
  text "Top Layer - Bottom Layer" at 184.506,67.083 h1.52
  text "260 Total" at 143.793,63.925 h1.52
  text ".Layer_Name" at 14.656,-21.806 h1.52
M17 Embedded Cavity:
  text ".Layer_Name" at 14.656,-21.806 h1.52
M18 Embedded Assembly:
  text ".Layer_Name" at 14.656,-21.806 h1.52
M19 Embedded Keepout:
  text ".Layer_Name" at 14.656,-21.806 h1.52

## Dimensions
0,-10.16 to 25.4,-10.16 on M2 Board Dimensions
0,0 to 37.305,35.484 on M2 Board Dimensions
0,0 to 80,0.016 on M2 Board Dimensions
